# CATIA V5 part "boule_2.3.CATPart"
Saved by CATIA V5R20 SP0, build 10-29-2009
Part number: boule_2.3
Bounding box of the stored display mesh (mm): x 2784.952 to 2880.768, y 1210.967 to 1310.959, z -501.873 to -401.877
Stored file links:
  D:\thinkmotion-MPB\Dropbox\MMS_GR3\CFAO_2010_bfoltzer\CFAO_bfoltzer\boule_2.3.CATPart
  D:\ecole\thinkmotion\Eolienne.CATProduct
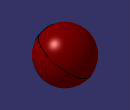
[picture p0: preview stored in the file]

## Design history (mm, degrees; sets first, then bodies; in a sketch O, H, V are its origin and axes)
External parameters (linked from other documents)
  External.rayon_barre = 20 mm
Set1
  Plane1: linked copy from another document
  Point1 to Point3: linked copy from another document
  Line1: linked copy from another document
  Point4: linked copy from another document
  Plane2: linked copy from another document
  Plane3: linked copy from another document
Body1 (main body)
  Sketch1 on Plane1, origin (0, 52.6643, 86.6621), H (1, 0, 0), V (0, -0.9134, 0.4071)
    arc A1 centre (2830.7782, -1322.8803) radius 50 from (2830.7782, -1272.8803) to (2830.7782, -1372.8803) ccw
    point P1 (2830.7782, -1322.8803)
    point P2 (2830.7782, -1272.8803)
    point P3 (2830.7782, -1372.8803)
    reference projected point E1 (2830.7782, -1272.8803) from Point1
    reference projected point E2 (2830.7782, -1372.8803) from Point2
    reference projected point E3 (2830.7782, -1322.8803) from Point3
    coincidence: P2 E1, P3 E2, E3 P1
  Shaft1: profile Sketch1, axis Line1, angle 360
  Sketch2 on {plane type Tangent, Support face of Shaft1 from Sketch1.A1, RefPoint Point4}, origin (2780.7782, 956.2569, -563.6246), H (0, 1, 0), V (0, 0, 1)
    point P1 (304.7085, 111.751)
    reference projected point E1 (304.7085, 111.751) from Point4
    coincidence: E1 P1
  Hole1: placed by Sketch2, at (2780.7782, 1260.9654, -451.8736) direction (1, 0, 0), diameter 40 {= External.rayon_barre *2}, up to Plane2
  Sketch3 on {plane type Tangent, Support face of Shaft1 from Sketch1.A1, RefPoint Point1}, origin (2830.7782, 456.5148, -2133.9803), H (1, 0, 0), V (0, -0.4071, -0.9134)
    point P1 (0, -1863.9002)
    reference projected point E1 (0, -1863.9002) from Point1
    coincidence: E1 P1
  Hole2: placed by Sketch3, at (2830.7782, 1215.2961, -431.5189) direction (0, 0.9134, -0.4071), diameter 40 {= External.rayon_barre *2}, up to Plane3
